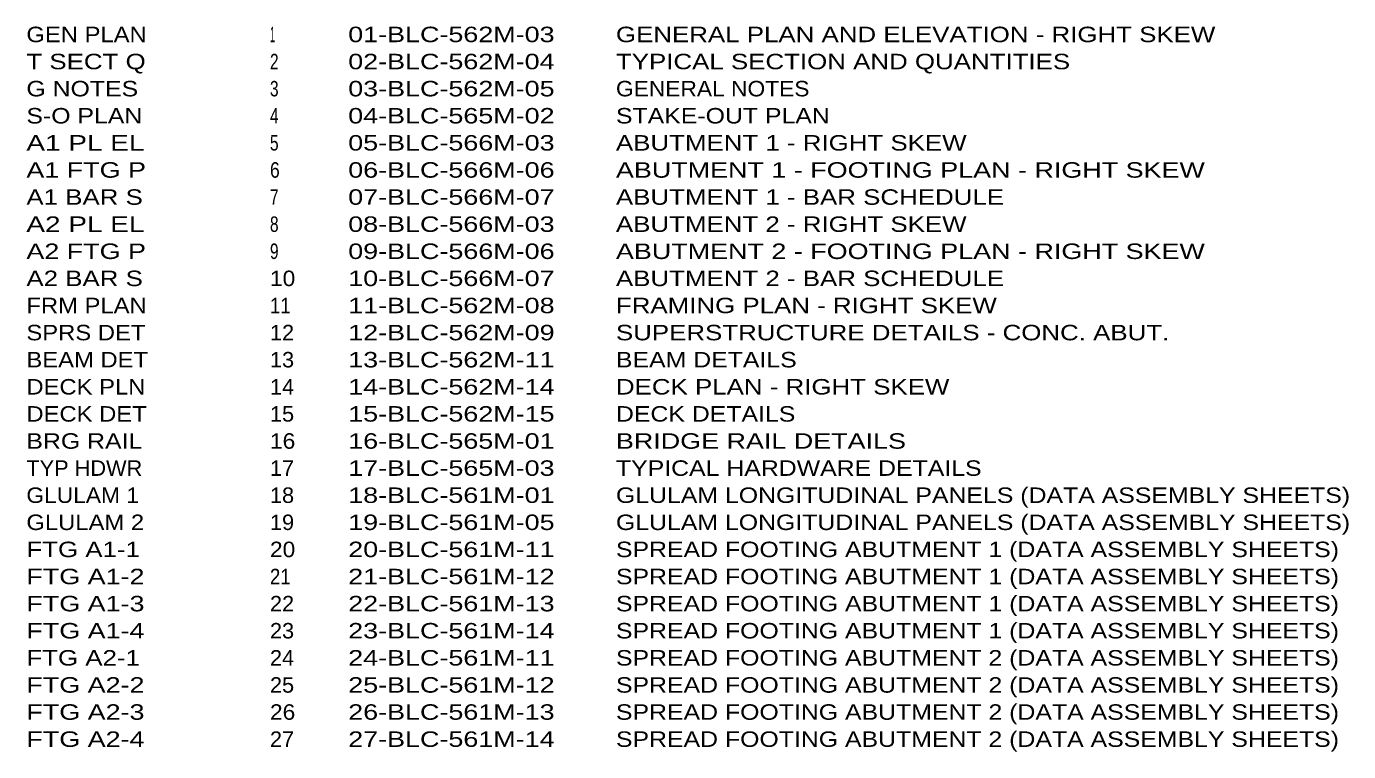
# Model space of a CAD drawing. Extents: x 177 to 463, y -304 to 17.
# Drawn here: x 222.5 to 462.8, y -304 to -172.3 of the extents above; entities that cross this region are included whole.
import ezdxf

# ---------------------------------------------------------------- set-up
doc = ezdxf.new("R2010")
doc.units = 0
doc.header["$LTSCALE"] = 0.048
doc.layers.add('62', color=7, linetype='Continuous')

msp = doc.modelspace()

# ---------------------------------------------------------------- texts
at = {"layer": '62'}
for s, width, p in [('GEN PLAN', 1.15, (222.53667, -175.15967)), ('1', 0.45, (266.79317, -175.15967)), ('01-BLC-562M-03', 1.3, (281.01367, -175.15967)), ('GENERAL PLAN AND ELEVATION - RIGHT SKEW', 1.25, (329.658, -175.15967)), ('T SECT Q', 1.25, (222.53667, -180.08158)), ('2', 0.75, (266.79317, -180.08158)), ('02-BLC-562M-04', 1.3, (281.01367, -180.08158)), ('TYPICAL SECTION AND QUANTITIES', 1.25, (329.658, -180.08158)), ('G NOTES ', 1.2, (222.53667, -185.0035)), ('3', 0.75, (266.79317, -185.0035)), ('03-BLC-562M-05', 1.3, (281.01367, -185.0035)), ('GENERAL NOTES', 1.1, (329.658, -185.0035)), ('S-O PLAN', 1.2, (222.53667, -189.92542)), ('4', 0.75, (266.79317, -189.92542)), ('04-BLC-565M-02', 1.3, (281.01367, -189.92542)), ('STAKE-OUT PLAN', 1.2, (329.658, -189.92542)), ('A1 PL EL', 1.35, (222.53667, -194.84733)), ('5', 0.75, (266.79317, -194.84733)), ('05-BLC-566M-03', 1.3, (281.01367, -194.84733)), ('ABUTMENT 1 - RIGHT SKEW', 1.25, (329.658, -194.84733)), ('A1 FTG P', 1.3, (222.53667, -199.76925)), ('6', 0.85, (266.79317, -199.76925)), ('06-BLC-566M-06', 1.3, (281.01367, -199.76925)), ('ABUTMENT 1 - FOOTING PLAN - RIGHT SKEW', 1.3, (329.658, -199.76925)), ('A1 BAR S', 1.25, (222.53667, -204.69117)), ('7', 0.75, (266.79317, -204.69117)), ('07-BLC-566M-07', 1.3, (281.01367, -204.69117)), ('ABUTMENT 1 - BAR SCHEDULE', 1.25, (329.658, -204.69117)), ('A2 PL EL', 1.35, (222.53667, -209.61308)), ('8', 0.75, (266.79317, -209.61308)), ('08-BLC-566M-03', 1.3, (281.01367, -209.61308)), ('ABUTMENT 2 - RIGHT SKEW', 1.25, (329.658, -209.61308)), ('A2 FTG P', 1.3, (222.53667, -214.535)), ('9', 0.75, (266.79317, -214.535)), ('09-BLC-566M-06', 1.3, (281.01367, -214.535)), ('ABUTMENT 2 - FOOTING PLAN - RIGHT SKEW', 1.3, (329.658, -214.535)), ('A2 BAR S', 1.25, (222.53667, -219.45692)), ('10', 1.1, (266.79317, -219.45692)), ('10-BLC-566M-07', 1.3, (281.01367, -219.45692)), ('ABUTMENT 2 - BAR SCHEDULE', 1.25, (329.658, -219.45692)), ('FRM PLAN', 1.15, (222.53667, -224.37883)), ('11', 0.9, (266.79317, -224.37883)), ('11-BLC-562M-08', 1.3, (281.01367, -224.37883)), ('FRAMING PLAN - RIGHT SKEW', 1.25, (329.658, -224.37883)), ('SPRS DET', 1.15, (222.53667, -229.30075)), ('12', 1.05, (266.79317, -229.30075)), ('12-BLC-562M-09', 1.3, (281.01367, -229.30075)), ('SUPERSTRUCTURE DETAILS - CONC. ABUT.', 1.25, (329.658, -229.30075)), ('BEAM DET', 1.15, (222.53667, -234.22267)), ('13', 1.05, (266.79317, -234.22267)), ('13-BLC-562M-11', 1.3, (281.01367, -234.22267)), ('BEAM DETAILS', 1.2, (329.658, -234.22267)), ('DECK PLN', 1.15, (222.53667, -239.14458)), ('14', 1.05, (266.79317, -239.14458)), ('14-BLC-562M-14', 1.3, (281.01367, -239.14458)), ('DECK PLAN - RIGHT SKEW', 1.25, (329.658, -239.14458)), ('DECK DET', 1.15, (222.53667, -244.0665)), ('15', 1.05, (266.79317, -244.0665)), ('15-BLC-562M-15', 1.3, (281.01367, -244.0665)), ('DECK DETAILS', 1.2, (329.658, -244.0665)), ('BRG RAIL', 1.2, (222.53667, -248.98842)), ('16', 1.1, (266.79317, -248.98842)), ('16-BLC-565M-01', 1.3, (281.01367, -248.98842)), ('BRIDGE RAIL DETAILS', 1.3, (329.658, -248.98842)), ('TYP HDWR', 1.05, (222.53667, -253.91033)), ('17', 1.05, (266.79317, -253.91033)), ('17-BLC-565M-03', 1.3, (281.01367, -253.91033)), ('TYPICAL HARDWARE DETAILS', 1.2, (329.658, -253.91033)), ('GLULAM 1', 1.1, (222.53667, -258.83225)), ('18', 1.05, (266.79317, -258.83225)), ('18-BLC-561M-01', 1.3, (281.01367, -258.83225)), ('GLULAM LONGITUDINAL PANELS (DATA ASSEMBLY SHEETS)', 1.2, (329.658, -258.83225)), ('GLULAM 2', 1.15, (222.53667, -263.75417)), ('19', 1.05, (266.79317, -263.75417)), ('19-BLC-561M-05', 1.3, (281.01367, -263.75417)), ('GLULAM LONGITUDINAL PANELS (DATA ASSEMBLY SHEETS)', 1.2, (329.658, -263.75417)), ('FTG A1-1', 1.25, (222.53667, -268.67608)), ('20', 1.1, (266.79317, -268.67608)), ('20-BLC-561M-11', 1.3, (281.01367, -268.67608)), ('SPREAD FOOTING ABUTMENT 1 (DATA ASSEMBLY SHEETS)', 1.2, (329.658, -268.67608)), ('FTG A1-2', 1.3, (222.53667, -273.598)), ('21', 0.9, (266.79317, -273.598)), ('21-BLC-561M-12', 1.3, (281.01367, -273.598)), ('SPREAD FOOTING ABUTMENT 1 (DATA ASSEMBLY SHEETS)', 1.2, (329.658, -273.598)), ('FTG A1-3', 1.3, (222.53667, -278.51992)), ('22', 1.05, (266.79317, -278.51992)), ('22-BLC-561M-13', 1.3, (281.01367, -278.51992)), ('SPREAD FOOTING ABUTMENT 1 (DATA ASSEMBLY SHEETS)', 1.2, (329.658, -278.51992)), ('FTG A1-4', 1.3, (222.53667, -283.44183)), ('23', 1.05, (266.79317, -283.44183)), ('23-BLC-561M-14', 1.3, (281.01367, -283.44183)), ('SPREAD FOOTING ABUTMENT 1 (DATA ASSEMBLY SHEETS)', 1.2, (329.658, -283.44183)), ('FTG A2-1', 1.25, (222.53667, -288.36375)), ('24', 1.05, (266.79317, -288.36375)), ('24-BLC-561M-11', 1.3, (281.01367, -288.36375)), ('SPREAD FOOTING ABUTMENT 2 (DATA ASSEMBLY SHEETS)', 1.2, (329.658, -288.36375)), ('FTG A2-2', 1.3, (222.53667, -293.28567)), ('25', 1.05, (266.79317, -293.28567)), ('25-BLC-561M-12', 1.3, (281.01367, -293.28567)), ('SPREAD FOOTING ABUTMENT 2 (DATA ASSEMBLY SHEETS)', 1.2, (329.658, -293.28567)), ('FTG A2-3', 1.3, (222.53667, -298.20758)), ('26', 1.1, (266.79317, -298.20758)), ('26-BLC-561M-13', 1.3, (281.01367, -298.20758)), ('SPREAD FOOTING ABUTMENT 2 (DATA ASSEMBLY SHEETS)', 1.2, (329.658, -298.20758)), ('FTG A2-4', 1.3, (222.53667, -303.1295)), ('27', 1.05, (266.79317, -303.1295)), ('27-BLC-561M-14', 1.3, (281.01367, -303.1295)), ('SPREAD FOOTING ABUTMENT 2 (DATA ASSEMBLY SHEETS)', 1.2, (329.658, -303.1295))]:
    msp.add_text(s, height=2.812, dxfattribs=dict(at, width=width)).set_placement(p)

doc.saveas('drawing.dxf')
